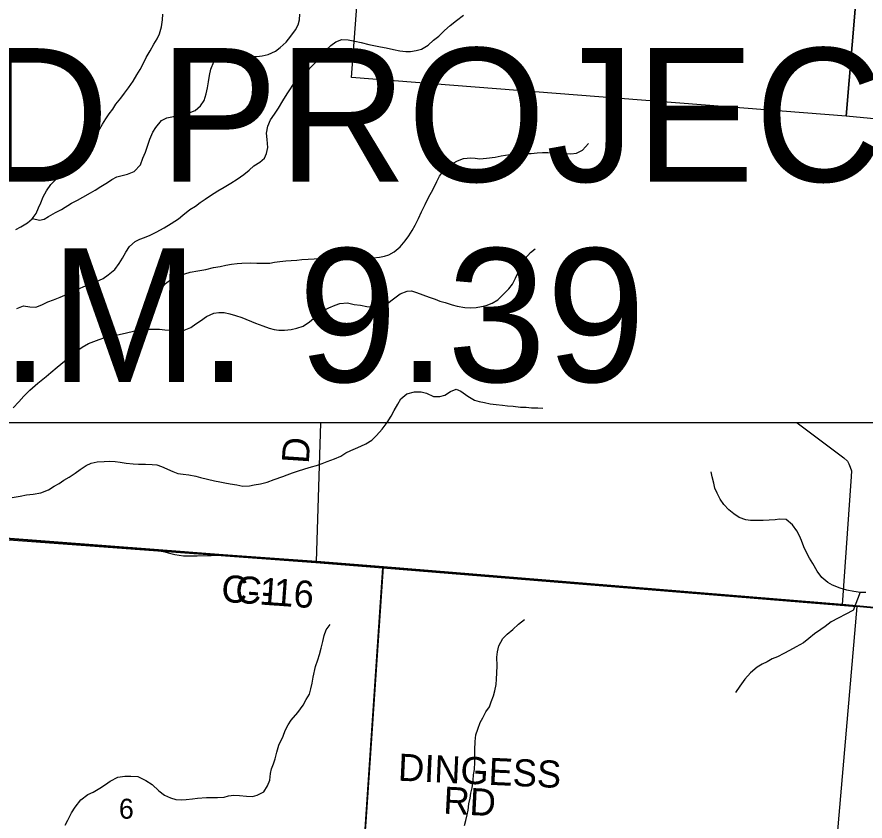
# Model space of a CAD drawing. Extents: x 0 to 42.5, y 0 to 22.
# Drawn here: x 5.56 to 6.449, y 18.534 to 19.377 of the extents above; entities that cross this region are included whole.
import ezdxf

# ---------------------------------------------------------------- set-up
doc = ezdxf.new("R2010")
doc.units = 0
for name, color, linetype in [('GM_X_County_Road', 7, 'Continuous'), ('GM_X_County_Road_Text', 7, 'Continuous'), ('GM_X_Interchange_Ramps', 7, 'Continuous'), ('GM_X_Minor_River', 7, 'Continuous'), ('GM_X_Section', 7, 'Continuous'), ('GM_X_Section_Text', 7, 'Continuous'), ('GM_X_Township', 7, 'Continuous'), ('GM_X_Township_Road', 7, 'Continuous'), ('GM_X_Township_Road_Text', 7, 'Continuous'), ('SH_Cut_Line', 7, 'Continuous'), ('SH_Text', 7, 'Continuous')]:
    doc.layers.add(name, color=color, linetype=linetype)

msp = doc.modelspace()

# ---------------------------------------------------------------- linework, layer by layer
at = {"layer": 'GM_X_County_Road'}
for p, q in [((5.8743, 18.80603), (5.94459, 18.80049)), ((5.94459, 18.80049), (6.42547, 18.76077))]:
    msp.add_line(p, q, dxfattribs=at)
for points in [[(5.4956, 18.83437), (5.53929, 18.83104), (5.70422, 18.81846)], [(5.70422, 18.81846), (5.71532, 18.8162), (5.71885, 18.81549), (5.7258, 18.81359), (5.73495, 18.81201), (5.74915, 18.81201), (5.76398, 18.81249), (5.77662, 18.81294)], [(5.77662, 18.81294), (5.77961, 18.81273), (5.8743, 18.80603)], [(6.42547, 18.76077), (6.65165, 18.73941), (6.84845, 18.72158), (6.85599, 18.72029), (6.86201, 18.71925)]]:
    msp.add_lwpolyline(points, dxfattribs=at)
at = {"layer": 'GM_X_Interchange_Ramps'}
msp.add_lwpolyline([(5.45275, 18.95149), (5.4438, 18.83893), (5.48124, 18.83572), (5.53918, 18.8313), (5.70411, 18.81873), (5.77651, 18.81321), (5.87419, 18.80629), (5.94448, 18.80075), (6.42536, 18.76104), (6.65154, 18.73968)], dxfattribs=at)
at = {"layer": 'GM_X_Minor_River'}
for points in [[(5.55904, 19.15427), (5.56457, 19.15725), (5.57144, 19.16136), (5.57642, 19.16567), (5.58047, 19.17133), (5.583, 19.177), (5.58534, 19.18249), (5.58768, 19.18854), (5.59117, 19.19477), (5.5958, 19.20156), (5.60328, 19.20889), (5.60903, 19.21415), (5.61534, 19.21845), (5.6205, 19.22257), (5.62703, 19.22972), (5.63261, 19.23707), (5.63801, 19.24423), (5.64226, 19.25103), (5.64574, 19.25745), (5.65019, 19.26481), (5.65367, 19.27048), (5.65714, 19.27576), (5.66099, 19.28066), (5.6639, 19.28575), (5.66909, 19.29197), (5.67313, 19.29724), (5.67737, 19.3029), (5.682, 19.31007), (5.68587, 19.31648), (5.68935, 19.32215), (5.69322, 19.32951), (5.69594, 19.33481), (5.7, 19.3416), (5.70369, 19.34878), (5.70716, 19.35425), (5.70988, 19.35955), (5.71186, 19.36674), (5.71289, 19.37414), (5.71334, 19.38003)], [(5.57669, 19.16605), (5.58399, 19.16407), (5.58874, 19.16535), (5.59351, 19.16796), (5.60076, 19.17206), (5.60687, 19.17541), (5.61757, 19.18213), (5.62367, 19.18511), (5.62958, 19.18827), (5.6376, 19.19275), (5.64237, 19.19554), (5.64829, 19.19947), (5.65517, 19.20357), (5.65994, 19.20694), (5.66491, 19.20974), (5.67061, 19.21101), (5.67631, 19.21246), (5.68336, 19.21524), (5.6897, 19.2222), (5.69243, 19.22901), (5.69516, 19.23563), (5.69713, 19.24188), (5.69968, 19.24907), (5.7028, 19.25645), (5.70608, 19.26135), (5.71185, 19.26851), (5.71739, 19.27149), (5.72442, 19.27293), (5.72936, 19.27421), (5.73544, 19.27528), (5.74248, 19.27748), (5.74724, 19.27933), (5.7528, 19.28402), (5.75665, 19.28968), (5.75863, 19.29669), (5.76003, 19.30294), (5.76105, 19.30939), (5.76227, 19.31603), (5.76348, 19.32248), (5.76679, 19.33004), (5.7733, 19.33491), (5.78165, 19.33615), (5.78678, 19.33666), (5.7936, 19.33621), (5.80042, 19.33575), (5.80649, 19.33588), (5.81198, 19.33563), (5.8173, 19.33633), (5.82376, 19.33797), (5.83139, 19.34149), (5.83636, 19.34524), (5.84268, 19.35087), (5.8475, 19.35728), (5.85232, 19.36388), (5.85503, 19.36917), (5.85642, 19.37428), (5.85687, 19.38017)], [(5.99704, 19.35298), (6.00259, 19.3571), (6.00853, 19.36293), (6.01466, 19.36837), (6.02117, 19.37362), (6.02844, 19.37924)], [(5.56016, 19.0716), (5.5672, 19.07419), (5.57383, 19.07316), (5.58008, 19.0729), (5.58637, 19.0755), (5.59285, 19.07866), (5.59856, 19.08068), (5.6058, 19.08345), (5.61285, 19.08661), (5.61933, 19.08939), (5.62429, 19.0918), (5.63229, 19.09514), (5.63763, 19.09755), (5.64372, 19.09995), (5.65058, 19.10311), (5.65612, 19.10685), (5.66301, 19.11228), (5.66745, 19.11869), (5.67112, 19.12416), (5.6746, 19.13058), (5.67827, 19.13644), (5.6844, 19.14169), (5.68917, 19.14411), (5.69412, 19.14614), (5.69984, 19.14836), (5.70613, 19.15152), (5.71452, 19.15599), (5.72197, 19.16066), (5.72962, 19.16571), (5.7344, 19.16945), (5.74167, 19.17545), (5.74759, 19.179), (5.75256, 19.18275), (5.75753, 19.18611), (5.76327, 19.19004), (5.7711, 19.19489), (5.77759, 19.19862), (5.78465, 19.20292), (5.79134, 19.20721), (5.79822, 19.21208), (5.80377, 19.21658), (5.80856, 19.22128), (5.81505, 19.22482), (5.81984, 19.22932), (5.82199, 19.23424), (5.8232, 19.2405), (5.82272, 19.24867), (5.82205, 19.25552), (5.82327, 19.26273), (5.82619, 19.26954), (5.83024, 19.27519), (5.83448, 19.28161), (5.83893, 19.28935), (5.84357, 19.29652), (5.84704, 19.3018), (5.85052, 19.30746), (5.85704, 19.31404), (5.86184, 19.31893), (5.8672, 19.32324), (5.87353, 19.33001), (5.87911, 19.33698), (5.88391, 19.34206), (5.88928, 19.34732), (5.89464, 19.35106), (5.90092, 19.35365), (5.90755, 19.35339), (5.91455, 19.35198), (5.92136, 19.35039), (5.92911, 19.34822), (5.9416, 19.34599), (5.94727, 19.34479), (5.95521, 19.34299), (5.96183, 19.34159), (5.96808, 19.34114), (5.97282, 19.34109), (5.97871, 19.34197), (5.98461, 19.34362), (5.99129, 19.34773), (5.99704, 19.35298)], [(5.69737, 19.04996), (5.69761, 19.05509), (5.6992, 19.06096), (5.70059, 19.06645), (5.7039, 19.07421), (5.70645, 19.08121), (5.71227, 19.09293), (5.71612, 19.09783), (5.72281, 19.10269), (5.73044, 19.10622), (5.73634, 19.10787), (5.74185, 19.10952), (5.74983, 19.11095), (5.75838, 19.11257), (5.76656, 19.11438), (5.77321, 19.11564), (5.77948, 19.11709), (5.78518, 19.11816), (5.79126, 19.11886), (5.79619, 19.11918), (5.80567, 19.11946), (5.81193, 19.11901), (5.81932, 19.11893), (5.82539, 19.11924), (5.83033, 19.11995), (5.83583, 19.12084), (5.84229, 19.12153), (5.84798, 19.12204), (5.85367, 19.12235), (5.85899, 19.12287), (5.86563, 19.12317), (5.87208, 19.12367), (5.87739, 19.124), (5.8829, 19.12432), (5.88897, 19.12501), (5.89485, 19.12513), (5.90623, 19.12539), (5.91172, 19.12514), (5.91741, 19.12489), (5.92233, 19.12445), (5.92745, 19.1244), (5.9339, 19.12471), (5.94035, 19.12521), (5.94548, 19.12629), (5.95024, 19.12795), (5.95578, 19.13093), (5.96191, 19.13618), (5.96729, 19.14258), (5.97133, 19.14786), (5.97481, 19.15333), (5.97791, 19.15881), (5.98121, 19.16599), (5.98432, 19.1728), (5.9884, 19.18074), (5.99209, 19.18849), (5.99499, 19.19358), (5.99791, 19.19963), (6.00043, 19.20455), (6.00334, 19.2104), (6.00758, 19.21587), (6.0139, 19.22169), (6.02211, 19.22654), (6.0284, 19.22894), (6.03599, 19.22943), (6.04072, 19.22919), (6.04564, 19.22856), (6.05267, 19.22925), (6.06159, 19.23029), (6.06805, 19.23174), (6.07698, 19.23316), (6.08211, 19.23367), (6.08799, 19.23418), (6.09368, 19.23412), (6.09937, 19.23425), (6.10563, 19.23475), (6.11113, 19.23507), (6.11682, 19.23501), (6.12326, 19.23474), (6.13103, 19.23447), (6.13577, 19.23404), (6.14088, 19.23379), (6.14677, 19.2343), (6.15325, 19.23765), (6.1594, 19.24442)], [(6.04744, 19.07349), (6.05238, 19.07458), (6.05867, 19.07717), (6.06459, 19.08071), (6.0761, 19.09199), (6.07976, 19.09708), (6.08306, 19.1035), (6.08694, 19.11144), (6.08947, 19.11712), (6.09315, 19.12392), (6.09873, 19.13031), (6.10351, 19.13406)], [(5.55648, 18.96732), (5.56243, 18.97372), (5.56762, 18.97974), (5.57376, 18.98576), (5.58219, 18.99326), (5.59099, 19.0002), (5.59578, 19.00433), (5.60267, 19.00995), (5.61014, 19.01614), (5.61703, 19.02196), (5.62277, 19.02664), (5.6287, 19.03114), (5.63519, 19.03468), (5.64091, 19.03709), (5.64643, 19.03912), (5.65233, 19.04114), (5.65708, 19.04223), (5.66259, 19.04331), (5.66753, 19.0442), (5.67533, 19.04602), (5.68236, 19.04784), (5.68977, 19.04947), (5.69642, 19.04997), (5.70988, 19.04982), (5.71537, 19.04919), (5.72029, 19.04895), (5.72541, 19.04851), (5.73052, 19.04827), (5.73565, 19.04897), (5.7427, 19.05174), (5.74786, 19.0553), (5.75283, 19.05866), (5.75914, 19.06315), (5.76676, 19.06649), (5.77189, 19.06739), (5.77757, 19.06732), (5.78363, 19.06593), (5.7893, 19.06434), (5.79609, 19.06199), (5.81025, 19.05613), (5.81798, 19.0532), (5.82478, 19.05103), (5.82989, 19.04946), (5.835, 19.04883), (5.84087, 19.04877), (5.84771, 19.04945), (5.8536, 19.05091), (5.86045, 19.05292), (5.86695, 19.0576), (5.87327, 19.06267), (5.88054, 19.06867), (5.88722, 19.07239), (5.89389, 19.07517), (5.89884, 19.07683), (5.907, 19.07731), (5.9138, 19.0759), (5.92043, 19.07488), (5.92705, 19.07348), (5.93444, 19.07302), (5.93937, 19.07353), (5.94412, 19.07462), (5.94909, 19.07723), (5.95502, 19.08172), (5.9619, 19.08697), (5.96933, 19.08974), (5.97407, 19.09006), (5.97917, 19.08849), (5.98578, 19.08595), (5.99239, 19.08359), (5.99862, 19.08125), (6.00371, 19.07929), (6.00919, 19.07771), (6.01675, 19.07535), (6.02185, 19.07415), (6.0298, 19.07273), (6.03624, 19.07228), (6.04174, 19.0726), (6.04744, 19.07349)], [(5.5552, 18.87347), (5.56356, 18.8749), (5.57021, 18.87615), (5.57742, 18.87683), (5.58521, 18.87808), (5.5934, 18.88141), (5.59951, 18.88533), (5.60448, 18.88813), (5.60963, 18.89149), (5.61498, 18.89466), (5.62128, 18.89878), (5.62664, 18.90271), (5.63294, 18.90701), (5.63809, 18.90923), (5.64455, 18.91068), (5.65176, 18.91117), (5.65745, 18.9113), (5.66333, 18.91105), (5.66844, 18.91042), (5.67487, 18.9094), (5.68226, 18.90856), (5.68775, 18.90831), (5.69515, 18.90823), (5.70216, 18.90796), (5.70689, 18.90753), (5.71199, 18.90576), (5.72387, 18.9005), (5.72916, 18.89836), (5.73465, 18.89773), (5.74052, 18.89728), (5.74771, 18.89568), (5.75262, 18.8943), (5.75999, 18.89251), (5.76756, 18.89091), (5.77286, 18.8899), (5.77834, 18.8887), (5.78383, 18.88769), (5.79083, 18.88647), (5.79707, 18.88526), (5.80428, 18.88575), (5.80903, 18.88646), (5.81549, 18.88772), (5.82253, 18.88954), (5.83014, 18.89212), (5.8389, 18.89544), (5.84366, 18.8971), (5.84918, 18.89932), (5.85432, 18.90098), (5.86212, 18.90355), (5.86916, 18.90538), (5.8743, 18.90684), (5.88039, 18.90905), (5.88553, 18.91109), (5.89334, 18.91385), (5.90001, 18.91663), (5.90517, 18.92018), (5.91031, 18.9226), (5.91508, 18.92482), (5.92098, 18.92723), (5.92613, 18.92964), (5.93243, 18.93338), (5.93742, 18.93826), (5.94318, 18.94485), (5.94839, 18.95201), (5.95263, 18.95862), (5.95574, 18.96466), (5.95961, 18.97127), (5.96289, 18.97675), (5.96921, 18.98219), (5.9772, 18.98419), (5.98403, 18.98431), (5.9897, 18.98291), (5.99705, 18.97941), (6.00368, 18.97915), (6.00882, 18.98062), (6.01474, 18.98435), (6.02065, 18.98695), (6.02575, 18.98499), (6.03289, 18.97959), (6.03986, 18.97553), (6.04477, 18.97414), (6.05044, 18.97294), (6.0565, 18.97173), (6.06274, 18.97071), (6.06918, 18.97026), (6.07448, 18.96964), (6.08054, 18.96919), (6.08831, 18.96816), (6.09399, 18.9679), (6.09967, 18.96746)], [(6.09967, 18.96746), (6.10631, 18.96739), (6.1118, 18.96714)], [(6.45026, 18.7738), (6.44457, 18.77386), (6.43775, 18.77469), (6.43019, 18.7763), (6.4232, 18.77827), (6.41546, 18.7814), (6.41037, 18.78412), (6.40399, 18.78951), (6.39933, 18.79621), (6.39468, 18.80405), (6.39133, 18.80979), (6.38836, 18.81495), (6.38521, 18.82163), (6.38264, 18.82831), (6.38061, 18.83309), (6.37801, 18.83824), (6.37335, 18.84457), (6.36659, 18.85015), (6.35977, 18.8506), (6.35502, 18.85009), (6.34876, 18.84958), (6.3425, 18.84927), (6.337, 18.84914), (6.32923, 18.84923), (6.32431, 18.85004), (6.31732, 18.8524), (6.31186, 18.85626), (6.30661, 18.8605), (6.30155, 18.86587), (6.29744, 18.87162), (6.29429, 18.87792), (6.29208, 18.88327), (6.291, 18.88822), (6.289, 18.89508), (6.28811, 18.90022)], [(6.44421, 18.7739), (6.43686, 18.75471)], [(6.43655, 18.75483), (6.41386, 18.74305), (6.40773, 18.73797), (6.40294, 18.73496), (6.39643, 18.73045), (6.39049, 18.72537), (6.38474, 18.72104), (6.37708, 18.71692), (6.37019, 18.71279), (6.36445, 18.7096), (6.35755, 18.70642), (6.352, 18.70418), (6.34664, 18.70118), (6.34166, 18.69856), (6.33649, 18.69556), (6.3294, 18.68934), (6.32346, 18.68292), (6.31809, 18.67536), (6.31348, 18.66894)], [(6.03088, 18.53479), (6.03242, 18.54048), (6.0332, 18.54541), (6.03417, 18.55224), (6.03533, 18.55793), (6.03629, 18.56344), (6.03745, 18.56894), (6.03843, 18.57691), (6.03901, 18.5826), (6.04017, 18.5881), (6.04038, 18.5957), (6.0402, 18.60083), (6.04041, 18.6088), (6.04081, 18.61735), (6.0414, 18.62456), (6.04332, 18.63025), (6.04602, 18.63726), (6.04871, 18.64237), (6.05197, 18.64861), (6.05581, 18.6539), (6.05735, 18.65921), (6.06004, 18.66546), (6.06139, 18.67058), (6.06255, 18.67741), (6.06295, 18.68272), (6.06353, 18.68956), (6.06374, 18.69696), (6.06357, 18.70589), (6.06396, 18.71159), (6.06551, 18.71766), (6.06954, 18.72541), (6.07433, 18.73013), (6.08027, 18.73502), (6.08602, 18.74049), (6.09254, 18.74538)], [(5.67331, 18.58126), (5.67981, 18.58102), (5.68708, 18.58078), (5.69529, 18.57654), (5.70198, 18.57232), (5.70904, 18.56581), (5.71496, 18.5612), (5.72127, 18.55831), (5.72681, 18.55675), (5.73274, 18.55614), (5.7379, 18.55648), (5.74441, 18.55738), (5.74976, 18.5581), (5.75895, 18.5588), (5.77042, 18.55871), (5.7775, 18.55904), (5.78228, 18.56034), (5.78783, 18.56106), (5.79357, 18.56101), (5.80084, 18.56001), (5.80715, 18.55978), (5.81231, 18.56107), (5.81921, 18.56482), (5.82305, 18.57087), (5.82555, 18.57693), (5.82613, 18.58376), (5.8271, 18.58889), (5.82922, 18.59419), (5.83095, 18.5993), (5.83288, 18.60613), (5.835, 18.61352), (5.83942, 18.62318), (5.84153, 18.62905), (5.8448, 18.63491), (5.84787, 18.63983), (5.85477, 18.64776), (5.86053, 18.65551), (5.86341, 18.66156), (5.86686, 18.66724), (5.8684, 18.67273), (5.86995, 18.6788), (5.87092, 18.68487), (5.87343, 18.69625), (5.87593, 18.70307), (5.87766, 18.70876), (5.8794, 18.71539), (5.88094, 18.72241), (5.8823, 18.72848), (5.88441, 18.73454), (5.88863, 18.74021)], [(5.61084, 18.52967), (5.61353, 18.53497), (5.61737, 18.54273), (5.6214, 18.54878), (5.62716, 18.55633), (5.63482, 18.56178), (5.64018, 18.56441), (5.64727, 18.56853), (5.6532, 18.57248), (5.65818, 18.57586), (5.66604, 18.58017), (5.67331, 18.58126)], [(6.02953, 18.52929), (6.03088, 18.53479)]]:
    msp.add_lwpolyline(points, dxfattribs=at)
at = {"layer": 'GM_X_Section'}
for points in [[(5.94892, 19.81768), (6.47172, 19.77233), (6.42948, 19.27339), (5.91121, 19.3138)], [(6.47172, 19.77233), (6.98695, 19.72796), (6.94317, 19.22409), (6.42948, 19.27339)], [(5.87382, 18.8051), (5.94404, 18.79959), (5.90839, 18.27246), (5.40504, 18.29767), (5.40881, 18.34747), (5.44269, 18.83716)], [(6.3846, 18.76355), (6.44097, 18.75889), (6.3966, 18.24824), (5.90839, 18.27246), (5.94404, 18.79959)]]:
    msp.add_lwpolyline(points, close=True, dxfattribs=at)
at = {"layer": 'GM_X_Township'}
msp.add_lwpolyline([(5.21422, 15.79865), (5.23885, 16.11392), (5.27199, 16.5652), (5.30219, 16.95892), (5.32269, 17.21064), (5.36305, 17.75335), (5.38697, 18.0749), (5.4438, 18.83893), (5.48124, 18.83572), (5.53918, 18.8313), (5.70411, 18.81873), (5.77651, 18.81321), (5.87419, 18.80629), (5.94448, 18.80075), (6.42536, 18.76104), (6.65154, 18.73968)], dxfattribs=at)
at = {"layer": 'GM_X_Township_Road'}
msp.add_line((5.8743, 18.80603), (5.87875, 18.95149), dxfattribs=at)
for points in [[(6.37817, 18.95149), (6.42708, 18.91493), (6.43087, 18.9113), (6.43257, 18.90862), (6.43388, 18.90519), (6.4352, 18.90119), (6.43498, 18.89547), (6.42547, 18.76077)], [(5.89196, 18.10067), (5.90408, 18.2393), (5.92637, 18.53333), (5.94459, 18.80049)]]:
    msp.add_lwpolyline(points, dxfattribs=at)
at = {"layer": 'SH_Cut_Line'}
for points in [[(6.65154, 18.73968), (6.42536, 18.76104), (5.94448, 18.80075), (5.87419, 18.80629), (5.77651, 18.81321), (5.70411, 18.81873), (5.53918, 18.8313), (5.48124, 18.83572), (5.4438, 18.83893), (5.45275, 18.95149)], [(5.45275, 18.95149), (5.4438, 18.83893), (5.48124, 18.83572), (5.53918, 18.8313), (5.70411, 18.81873), (5.77651, 18.81321), (5.87419, 18.80629), (5.94448, 18.80075), (6.42536, 18.76104), (6.65154, 18.73968)]]:
    msp.add_lwpolyline(points, dxfattribs=at)
at = {"layer": 'SH_Text'}
msp.add_lwpolyline([(5.06974, 19.405), (6.77517, 19.405), (6.77517, 18.95149), (5.06974, 18.95149)], close=True, dxfattribs=at)

# ---------------------------------------------------------------- texts
at = {"layer": 'GM_X_County_Road_Text'}
for s, rotation, p in [('C-1', 355.88146, (5.77388, 18.76411)), ('C-16', 355.88964, (5.78849, 18.7631))]:
    msp.add_text(s, height=0.028409, rotation=rotation, dxfattribs=at).set_placement(p)
at = {"layer": 'GM_X_Section_Text'}
msp.add_text('6', height=0.02093, rotation=0.00001, dxfattribs=at).set_placement((5.66724, 18.53653))
at = {"layer": 'GM_X_Township_Road_Text'}
for s, height, rotation, p in [('D', 0.02841, 86.19415, (5.86623, 18.90826)), ('DINGESS', 0.028409, 357.39761, (5.95941, 18.57643)), ('RD', 0.028409, 357.03874, (6.00688, 18.54188))]:
    msp.add_text(s, height=height, rotation=rotation, dxfattribs=at).set_placement(p)
at = {"layer": 'SH_Text'}
for s, p in [('END PROJECT', (5.26202, 19.20458)), ('S.L.M. 9.39', (5.26202, 18.99458))]:
    msp.add_text(s, height=0.14, dxfattribs=at).set_placement(p)

doc.saveas('drawing.dxf')
